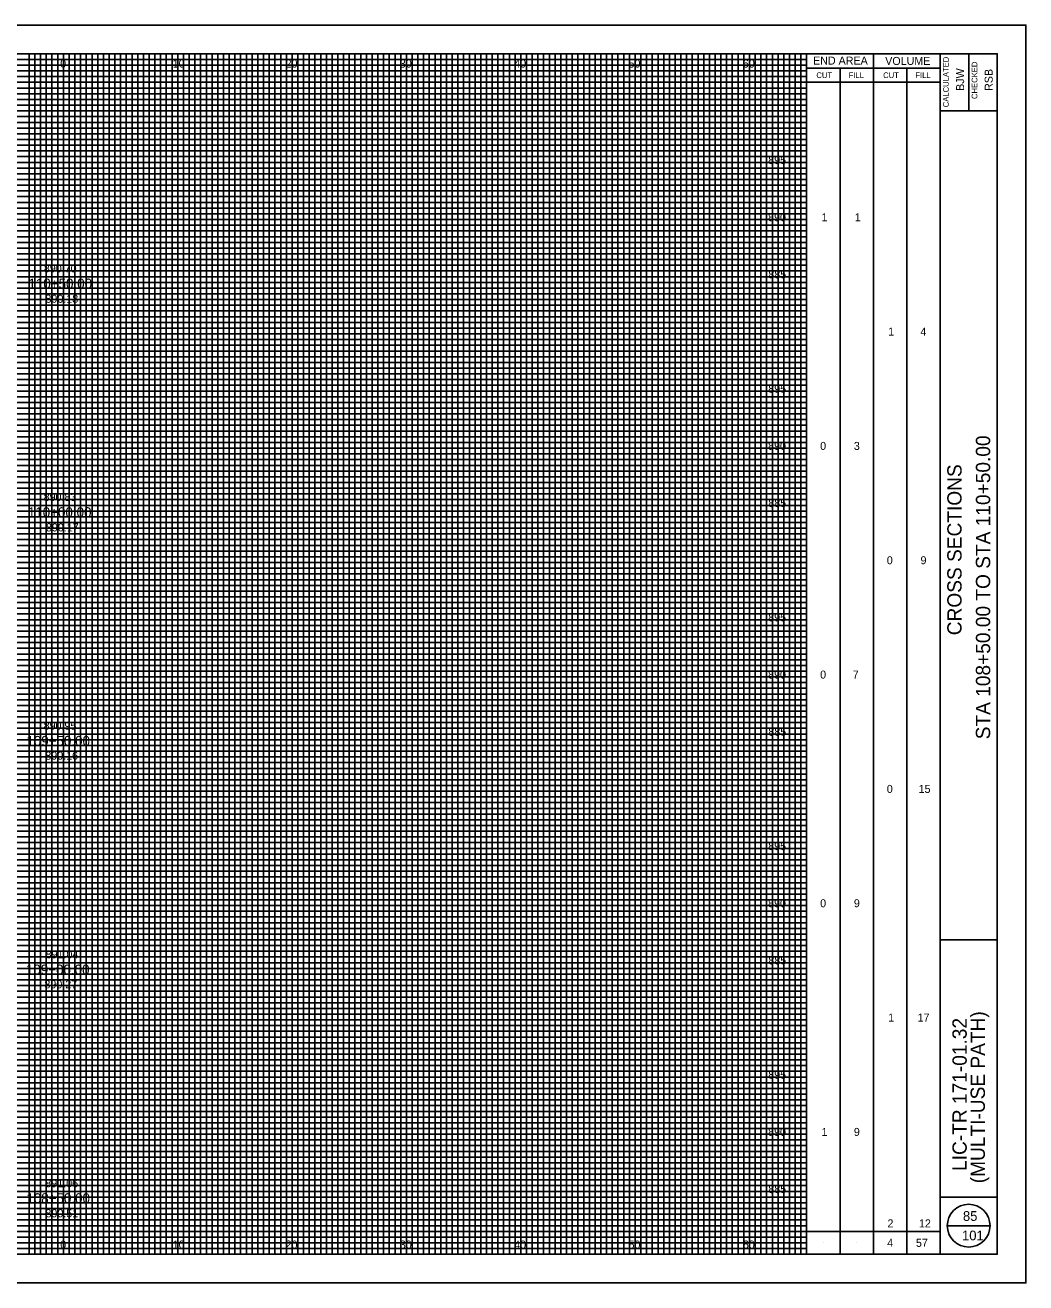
# Model space of a CAD drawing. Extents: x -10 to 160, y -2 to 3672.
# Drawn here: x 72.5 to 160, y 1837.5 to 1947.5 of the extents above; entities that cross this region are included whole.
import ezdxf

# ---------------------------------------------------------------- set-up
doc = ezdxf.new("R2010")
doc.units = 0
for name, color, linetype in [('SH_Border', 7, 'Continuous'), ('SH_Cut_Line', 7, 'Continuous'), ('SH_Data', 7, 'Continuous'), ('SH_Major_Grid_Line', 7, 'Continuous'), ('SH_Minor_Grid_Line', 7, 'Continuous'), ('SH_Text', 7, 'Continuous'), ('TX_P_10', 7, 'Continuous'), ('TX_X_10', 7, 'Continuous')]:
    doc.layers.add(name, color=color, linetype=linetype)

msp = doc.modelspace()

# ---------------------------------------------------------------- linework, layer by layer
at = {"layer": 'SH_Border'}
for p, q in [((152.5, 1840), (152.5, 1945)), ((155, 1945), (155, 1940)), ((152.5, 1940), (157.5, 1940)), ((152.5, 1867.5), (157.5, 1867.5)), ((152.5, 1845), (157.5, 1845))]:
    msp.add_line(p, q, dxfattribs=at)
msp.add_lwpolyline([(0, 1945), (157.5, 1945), (157.5, 1840), (0, 1840)], close=True, dxfattribs=at)
at = {"layer": 'SH_Cut_Line'}
msp.add_lwpolyline([(-10, 1837.5), (160, 1837.5), (160, 1947.5), (-10, 1947.5)], close=True, dxfattribs=at)
at = {"layer": 'SH_Data'}
for p, q in [((140.83, 1840), (140.83, 1945)), ((146.67, 1840), (146.67, 1945)), ((140.83, 1943.75), (152.5, 1943.75)), ((143.75, 1840), (143.75, 1943.75)), ((149.58, 1840), (149.58, 1943.75)), ((140.83, 1942.5), (152.5, 1942.5)), ((140.83, 1842), (152.5, 1842)), ((153.12, 1842.5), (156.88, 1842.5)), ((142.29, 1841), (142.29, 1841)), ((145.21, 1841), (145.21, 1841)), ((148.12, 1841), (148.12, 1841)), ((151.04, 1841), (151.04, 1841))]:
    msp.add_line(p, q, dxfattribs=at)
msp.add_circle((155, 1842.5), 1.87, dxfattribs=at)
at = {"layer": 'SH_Major_Grid_Line'}
for p, q in [((75.83, 1840), (75.83, 1945)), ((80.83, 1840), (80.83, 1945)), ((85.83, 1840), (85.83, 1945)), ((90.83, 1840), (90.83, 1945)), ((95.83, 1840), (95.83, 1945)), ((100.83, 1840), (100.83, 1945)), ((105.83, 1840), (105.83, 1945)), ((110.83, 1840), (110.83, 1945)), ((115.83, 1840), (115.83, 1945)), ((120.83, 1840), (120.83, 1945)), ((125.83, 1840), (125.83, 1945)), ((130.83, 1840), (130.83, 1945)), ((135.83, 1840), (135.83, 1945)), ((5.83, 1940), (140.83, 1940)), ((5.83, 1935), (140.83, 1935)), ((5.83, 1930), (140.83, 1930)), ((5.83, 1925), (140.83, 1925)), ((5.83, 1920), (140.83, 1920)), ((5.83, 1915), (140.83, 1915)), ((5.83, 1910), (140.83, 1910)), ((5.83, 1905), (140.83, 1905)), ((5.83, 1900), (140.83, 1900)), ((5.83, 1895), (140.83, 1895)), ((5.83, 1890), (140.83, 1890)), ((5.83, 1885), (140.83, 1885)), ((5.83, 1880), (140.83, 1880)), ((5.83, 1875), (140.83, 1875)), ((5.83, 1870), (140.83, 1870)), ((5.83, 1865), (140.83, 1865)), ((5.83, 1860), (140.83, 1860)), ((5.83, 1855), (140.83, 1855)), ((5.83, 1850), (140.83, 1850)), ((5.83, 1845), (140.83, 1845))]:
    msp.add_line(p, q, dxfattribs=at)
at = {"layer": 'SH_Minor_Grid_Line'}
for p, q in [((72.83, 1840), (72.83, 1945)), ((73.33, 1840), (73.33, 1945)), ((73.83, 1840), (73.83, 1945)), ((74.33, 1840), (74.33, 1945)), ((74.83, 1840), (74.83, 1945)), ((75.33, 1840), (75.33, 1945)), ((76.33, 1840), (76.33, 1945)), ((76.83, 1840), (76.83, 1945)), ((77.33, 1840), (77.33, 1945)), ((77.83, 1840), (77.83, 1945)), ((78.33, 1840), (78.33, 1945)), ((78.83, 1840), (78.83, 1945)), ((79.33, 1840), (79.33, 1945)), ((79.83, 1840), (79.83, 1945)), ((80.33, 1840), (80.33, 1945)), ((81.33, 1840), (81.33, 1945)), ((81.83, 1840), (81.83, 1945)), ((82.33, 1840), (82.33, 1945)), ((82.83, 1840), (82.83, 1945)), ((83.33, 1840), (83.33, 1945)), ((83.83, 1840), (83.83, 1945)), ((84.33, 1840), (84.33, 1945)), ((84.83, 1840), (84.83, 1945)), ((85.33, 1840), (85.33, 1945)), ((86.33, 1840), (86.33, 1945)), ((86.83, 1840), (86.83, 1945)), ((87.33, 1840), (87.33, 1945)), ((87.83, 1840), (87.83, 1945)), ((88.33, 1840), (88.33, 1945)), ((88.83, 1840), (88.83, 1945)), ((89.33, 1840), (89.33, 1945)), ((89.83, 1840), (89.83, 1945)), ((90.33, 1840), (90.33, 1945)), ((91.33, 1840), (91.33, 1945)), ((91.83, 1840), (91.83, 1945)), ((92.33, 1840), (92.33, 1945)), ((92.83, 1840), (92.83, 1945)), ((93.33, 1840), (93.33, 1945)), ((93.83, 1840), (93.83, 1945)), ((94.33, 1840), (94.33, 1945)), ((94.83, 1840), (94.83, 1945)), ((95.33, 1840), (95.33, 1945)), ((96.33, 1840), (96.33, 1945)), ((96.83, 1840), (96.83, 1945)), ((97.33, 1840), (97.33, 1945)), ((97.83, 1840), (97.83, 1945)), ((98.33, 1840), (98.33, 1945)), ((98.83, 1840), (98.83, 1945)), ((99.33, 1840), (99.33, 1945)), ((99.83, 1840), (99.83, 1945)), ((100.33, 1840), (100.33, 1945)), ((101.33, 1840), (101.33, 1945)), ((101.83, 1840), (101.83, 1945)), ((102.33, 1840), (102.33, 1945)), ((102.83, 1840), (102.83, 1945)), ((103.33, 1840), (103.33, 1945)), ((103.83, 1840), (103.83, 1945)), ((104.33, 1840), (104.33, 1945)), ((104.83, 1840), (104.83, 1945)), ((105.33, 1840), (105.33, 1945)), ((106.33, 1840), (106.33, 1945)), ((106.83, 1840), (106.83, 1945)), ((107.33, 1840), (107.33, 1945)), ((107.83, 1840), (107.83, 1945)), ((108.33, 1840), (108.33, 1945)), ((108.83, 1840), (108.83, 1945)), ((109.33, 1840), (109.33, 1945)), ((109.83, 1840), (109.83, 1945)), ((110.33, 1840), (110.33, 1945)), ((111.33, 1840), (111.33, 1945)), ((111.83, 1840), (111.83, 1945)), ((112.33, 1840), (112.33, 1945)), ((112.83, 1840), (112.83, 1945)), ((113.33, 1840), (113.33, 1945)), ((113.83, 1840), (113.83, 1945)), ((114.33, 1840), (114.33, 1945)), ((114.83, 1840), (114.83, 1945)), ((115.33, 1840), (115.33, 1945)), ((116.33, 1840), (116.33, 1945)), ((116.83, 1840), (116.83, 1945)), ((117.33, 1840), (117.33, 1945)), ((117.83, 1840), (117.83, 1945)), ((118.33, 1840), (118.33, 1945)), ((118.83, 1840), (118.83, 1945)), ((119.33, 1840), (119.33, 1945)), ((119.83, 1840), (119.83, 1945)), ((120.33, 1840), (120.33, 1945)), ((121.33, 1840), (121.33, 1945)), ((121.83, 1840), (121.83, 1945)), ((122.33, 1840), (122.33, 1945)), ((122.83, 1840), (122.83, 1945)), ((123.33, 1840), (123.33, 1945)), ((123.83, 1840), (123.83, 1945)), ((124.33, 1840), (124.33, 1945)), ((124.83, 1840), (124.83, 1945)), ((125.33, 1840), (125.33, 1945)), ((126.33, 1840), (126.33, 1945)), ((126.83, 1840), (126.83, 1945)), ((127.33, 1840), (127.33, 1945)), ((127.83, 1840), (127.83, 1945)), ((128.33, 1840), (128.33, 1945)), ((128.83, 1840), (128.83, 1945)), ((129.33, 1840), (129.33, 1945)), ((129.83, 1840), (129.83, 1945)), ((130.33, 1840), (130.33, 1945)), ((131.33, 1840), (131.33, 1945)), ((131.83, 1840), (131.83, 1945)), ((132.33, 1840), (132.33, 1945)), ((132.83, 1840), (132.83, 1945)), ((133.33, 1840), (133.33, 1945)), ((133.83, 1840), (133.83, 1945)), ((134.33, 1840), (134.33, 1945)), ((134.83, 1840), (134.83, 1945)), ((135.33, 1840), (135.33, 1945)), ((136.33, 1840), (136.33, 1945)), ((136.83, 1840), (136.83, 1945)), ((137.33, 1840), (137.33, 1945)), ((137.83, 1840), (137.83, 1945)), ((138.33, 1840), (138.33, 1945)), ((138.83, 1840), (138.83, 1945)), ((139.33, 1840), (139.33, 1945)), ((139.83, 1840), (139.83, 1945)), ((140.33, 1840), (140.33, 1945)), ((5.83, 1944.5), (140.83, 1944.5)), ((5.83, 1944), (140.83, 1944)), ((5.83, 1943.5), (140.83, 1943.5)), ((5.83, 1943), (140.83, 1943)), ((5.83, 1942.5), (140.83, 1942.5)), ((5.83, 1942), (140.83, 1942)), ((5.83, 1941.5), (140.83, 1941.5)), ((5.83, 1941), (140.83, 1941)), ((5.83, 1940.5), (140.83, 1940.5)), ((5.83, 1939.5), (140.83, 1939.5)), ((5.83, 1939), (140.83, 1939)), ((5.83, 1938.5), (140.83, 1938.5)), ((5.83, 1938), (140.83, 1938)), ((5.83, 1937.5), (140.83, 1937.5)), ((5.83, 1937), (140.83, 1937)), ((5.83, 1936.5), (140.83, 1936.5)), ((5.83, 1936), (140.83, 1936)), ((5.83, 1935.5), (140.83, 1935.5)), ((5.83, 1934.5), (140.83, 1934.5)), ((5.83, 1934), (140.83, 1934)), ((5.83, 1933.5), (140.83, 1933.5)), ((5.83, 1933), (140.83, 1933)), ((5.83, 1932.5), (140.83, 1932.5)), ((5.83, 1932), (140.83, 1932)), ((5.83, 1931.5), (140.83, 1931.5)), ((5.83, 1931), (140.83, 1931)), ((5.83, 1930.5), (140.83, 1930.5)), ((5.83, 1929.5), (140.83, 1929.5)), ((5.83, 1929), (140.83, 1929)), ((5.83, 1928.5), (140.83, 1928.5)), ((5.83, 1928), (140.83, 1928)), ((5.83, 1927.5), (140.83, 1927.5)), ((5.83, 1927), (140.83, 1927)), ((5.83, 1926.5), (140.83, 1926.5)), ((5.83, 1926), (140.83, 1926)), ((5.83, 1925.5), (140.83, 1925.5)), ((5.83, 1924.5), (140.83, 1924.5)), ((5.83, 1924), (140.83, 1924)), ((5.83, 1923.5), (140.83, 1923.5)), ((5.83, 1923), (140.83, 1923)), ((5.83, 1922.5), (140.83, 1922.5)), ((5.83, 1922), (140.83, 1922)), ((5.83, 1921.5), (140.83, 1921.5)), ((5.83, 1921), (140.83, 1921)), ((5.83, 1920.5), (140.83, 1920.5)), ((5.83, 1919.5), (140.83, 1919.5)), ((5.83, 1919), (140.83, 1919)), ((5.83, 1918.5), (140.83, 1918.5)), ((5.83, 1918), (140.83, 1918)), ((5.83, 1917.5), (140.83, 1917.5)), ((5.83, 1917), (140.83, 1917)), ((5.83, 1916.5), (140.83, 1916.5)), ((5.83, 1916), (140.83, 1916)), ((5.83, 1915.5), (140.83, 1915.5)), ((5.83, 1914.5), (140.83, 1914.5)), ((5.83, 1914), (140.83, 1914)), ((5.83, 1913.5), (140.83, 1913.5)), ((5.83, 1913), (140.83, 1913)), ((5.83, 1912.5), (140.83, 1912.5)), ((5.83, 1912), (140.83, 1912)), ((5.83, 1911.5), (140.83, 1911.5)), ((5.83, 1911), (140.83, 1911)), ((5.83, 1910.5), (140.83, 1910.5)), ((5.83, 1909.5), (140.83, 1909.5)), ((5.83, 1909), (140.83, 1909)), ((5.83, 1908.5), (140.83, 1908.5)), ((5.83, 1908), (140.83, 1908)), ((5.83, 1907.5), (140.83, 1907.5)), ((5.83, 1907), (140.83, 1907)), ((5.83, 1906.5), (140.83, 1906.5)), ((5.83, 1906), (140.83, 1906)), ((5.83, 1905.5), (140.83, 1905.5)), ((5.83, 1904.5), (140.83, 1904.5)), ((5.83, 1904), (140.83, 1904)), ((5.83, 1903.5), (140.83, 1903.5)), ((5.83, 1903), (140.83, 1903)), ((5.83, 1902.5), (140.83, 1902.5)), ((5.83, 1902), (140.83, 1902)), ((5.83, 1901.5), (140.83, 1901.5)), ((5.83, 1901), (140.83, 1901)), ((5.83, 1900.5), (140.83, 1900.5)), ((5.83, 1899.5), (140.83, 1899.5)), ((5.83, 1899), (140.83, 1899)), ((5.83, 1898.5), (140.83, 1898.5)), ((5.83, 1898), (140.83, 1898)), ((5.83, 1897.5), (140.83, 1897.5)), ((5.83, 1897), (140.83, 1897)), ((5.83, 1896.5), (140.83, 1896.5)), ((5.83, 1896), (140.83, 1896)), ((5.83, 1895.5), (140.83, 1895.5)), ((5.83, 1894.5), (140.83, 1894.5)), ((5.83, 1894), (140.83, 1894)), ((5.83, 1893.5), (140.83, 1893.5)), ((5.83, 1893), (140.83, 1893)), ((5.83, 1892.5), (140.83, 1892.5)), ((5.83, 1892), (140.83, 1892)), ((5.83, 1891.5), (140.83, 1891.5)), ((5.83, 1891), (140.83, 1891)), ((5.83, 1890.5), (140.83, 1890.5)), ((5.83, 1889.5), (140.83, 1889.5)), ((5.83, 1889), (140.83, 1889)), ((5.83, 1888.5), (140.83, 1888.5)), ((5.83, 1888), (140.83, 1888)), ((5.83, 1887.5), (140.83, 1887.5)), ((5.83, 1887), (140.83, 1887)), ((5.83, 1886.5), (140.83, 1886.5)), ((5.83, 1886), (140.83, 1886)), ((5.83, 1885.5), (140.83, 1885.5)), ((5.83, 1884.5), (140.83, 1884.5)), ((5.83, 1884), (140.83, 1884)), ((5.83, 1883.5), (140.83, 1883.5)), ((5.83, 1883), (140.83, 1883)), ((5.83, 1882.5), (140.83, 1882.5)), ((5.83, 1882), (140.83, 1882)), ((5.83, 1881.5), (140.83, 1881.5)), ((5.83, 1881), (140.83, 1881)), ((5.83, 1880.5), (140.83, 1880.5)), ((5.83, 1879.5), (140.83, 1879.5)), ((5.83, 1879), (140.83, 1879)), ((5.83, 1878.5), (140.83, 1878.5)), ((5.83, 1878), (140.83, 1878)), ((5.83, 1877.5), (140.83, 1877.5)), ((5.83, 1877), (140.83, 1877)), ((5.83, 1876.5), (140.83, 1876.5)), ((5.83, 1876), (140.83, 1876)), ((5.83, 1875.5), (140.83, 1875.5)), ((5.83, 1874.5), (140.83, 1874.5)), ((5.83, 1874), (140.83, 1874)), ((5.83, 1873.5), (140.83, 1873.5)), ((5.83, 1873), (140.83, 1873)), ((5.83, 1872.5), (140.83, 1872.5)), ((5.83, 1872), (140.83, 1872)), ((5.83, 1871.5), (140.83, 1871.5)), ((5.83, 1871), (140.83, 1871)), ((5.83, 1870.5), (140.83, 1870.5)), ((5.83, 1869.5), (140.83, 1869.5)), ((5.83, 1869), (140.83, 1869)), ((5.83, 1868.5), (140.83, 1868.5)), ((5.83, 1868), (140.83, 1868)), ((5.83, 1867.5), (140.83, 1867.5)), ((5.83, 1867), (140.83, 1867)), ((5.83, 1866.5), (140.83, 1866.5)), ((5.83, 1866), (140.83, 1866)), ((5.83, 1865.5), (140.83, 1865.5)), ((5.83, 1864.5), (140.83, 1864.5)), ((5.83, 1864), (140.83, 1864)), ((5.83, 1863.5), (140.83, 1863.5)), ((5.83, 1863), (140.83, 1863)), ((5.83, 1862.5), (140.83, 1862.5)), ((5.83, 1862), (140.83, 1862)), ((5.83, 1861.5), (140.83, 1861.5)), ((5.83, 1861), (140.83, 1861)), ((5.83, 1860.5), (140.83, 1860.5)), ((5.83, 1859.5), (140.83, 1859.5)), ((5.83, 1859), (140.83, 1859)), ((5.83, 1858.5), (140.83, 1858.5)), ((5.83, 1858), (140.83, 1858)), ((5.83, 1857.5), (140.83, 1857.5)), ((5.83, 1857), (140.83, 1857)), ((5.83, 1856.5), (140.83, 1856.5)), ((5.83, 1856), (140.83, 1856)), ((5.83, 1855.5), (140.83, 1855.5)), ((5.83, 1854.5), (140.83, 1854.5)), ((5.83, 1854), (140.83, 1854)), ((5.83, 1853.5), (140.83, 1853.5)), ((5.83, 1853), (140.83, 1853)), ((5.83, 1852.5), (140.83, 1852.5)), ((5.83, 1852), (140.83, 1852)), ((5.83, 1851.5), (140.83, 1851.5)), ((5.83, 1851), (140.83, 1851)), ((5.83, 1850.5), (140.83, 1850.5)), ((5.83, 1849.5), (140.83, 1849.5)), ((5.83, 1849), (140.83, 1849)), ((5.83, 1848.5), (140.83, 1848.5)), ((5.83, 1848), (140.83, 1848)), ((5.83, 1847.5), (140.83, 1847.5)), ((5.83, 1847), (140.83, 1847)), ((5.83, 1846.5), (140.83, 1846.5)), ((5.83, 1846), (140.83, 1846)), ((5.83, 1845.5), (140.83, 1845.5)), ((5.83, 1844.5), (140.83, 1844.5)), ((5.83, 1844), (140.83, 1844)), ((5.83, 1843.5), (140.83, 1843.5)), ((5.83, 1843), (140.83, 1843)), ((5.83, 1842.5), (140.83, 1842.5)), ((5.83, 1842), (140.83, 1842)), ((5.83, 1841.5), (140.83, 1841.5)), ((5.83, 1841), (140.83, 1841)), ((5.83, 1840.5), (140.83, 1840.5))]:
    msp.add_line(p, q, dxfattribs=at)

# ---------------------------------------------------------------- texts
at = {"layer": 'SH_Data'}
for s, height, p in [('END AREA', 0.7, (141.39, 1944.05)), ('VOLUME', 0.7, (147.7, 1944.02)), ('CUT', 0.5, (141.68, 1942.87)), ('FILL', 0.5, (144.5, 1942.87)), ('CUT', 0.5, (147.52, 1942.87)), ('FILL', 0.5, (150.34, 1942.87)), ('85', 0.85, (154.5, 1842.92)), ('101', 0.85, (154.42, 1841.22))]:
    msp.add_text(s, height=height, dxfattribs=at).set_placement(p)
for s, height, p in [('CALCULATED', 0.5, (153.26, 1940.32)), ('BJW', 0.7, (154.6, 1941.75)), ('CHECKED', 0.5, (155.76, 1941.04)), ('RSB', 0.7, (157.1, 1941.75)), ('STA 108+50.00 TO STA 110+50.00', 1.25, (156.88, 1885.04)), ('CROSS SECTIONS', 1.25, (154.38, 1894.14)), ('LIC-TR 171-01.32', 1.25, (154.83, 1847.29)), ('(MULTI-USE PATH)', 1.25, (156.42, 1846.21))]:
    msp.add_text(s, height=height, rotation=90, dxfattribs=at).set_placement(p)
at = {"layer": 'SH_Text'}
for s, height, p in [('0', 0.7, (75.55, 1943.79)), ('10', 0.7, (85.39, 1943.79)), ('20', 0.7, (95.26, 1943.79)), ('30', 0.7, (105.25, 1943.79)), ('40', 0.7, (115.25, 1943.79)), ('50', 0.7, (125.25, 1943.79)), ('60', 0.7, (135.25, 1943.79)), ('895', 0.7, (137.47, 1935.35)), ('890', 0.7, (137.46, 1930.35)), ('1', 0.7, (142.13, 1930.35)), ('1', 0.7, (145.04, 1930.35)), ('110+50.00', 0.875, (72.77, 1924.46)), ('885', 0.7, (137.48, 1925.35)), ('1', 0.7, (147.96, 1920.35)), ('4', 0.7, (150.78, 1920.35)), ('895', 0.7, (137.47, 1915.35)), ('890', 0.7, (137.46, 1910.35)), ('0', 0.7, (142.01, 1910.35)), ('3', 0.7, (144.96, 1910.35)), ('110+00.00', 0.875, (72.72, 1904.46)), ('885', 0.7, (137.48, 1905.35)), ('0', 0.7, (147.84, 1900.35)), ('9', 0.7, (150.79, 1900.35)), ('895', 0.7, (137.47, 1895.35)), ('890', 0.7, (137.46, 1890.35)), ('0', 0.7, (142.01, 1890.35)), ('7', 0.7, (144.86, 1890.35)), ('885', 0.7, (137.48, 1885.35)), ('109+50.00', 0.875, (72.59, 1884.46)), ('0', 0.7, (147.84, 1880.35)), ('15', 0.7, (150.62, 1880.35)), ('895', 0.7, (137.47, 1875.35)), ('890', 0.7, (137.46, 1870.35)), ('0', 0.7, (142.01, 1870.35)), ('9', 0.7, (144.96, 1870.35)), ('885', 0.7, (137.48, 1865.35)), ('109+00.00', 0.875, (72.55, 1864.46)), ('1', 0.7, (147.96, 1860.35)), ('17', 0.7, (150.53, 1860.35)), ('895', 0.7, (137.47, 1855.35)), ('890', 0.7, (137.46, 1850.35)), ('1', 0.7, (142.13, 1850.35)), ('9', 0.7, (144.96, 1850.35)), ('885', 0.7, (137.48, 1845.35)), ('108+50.00', 0.875, (72.59, 1844.46)), ('2', 0.7, (147.9, 1842.35)), ('12', 0.7, (150.65, 1842.35)), ('0', 0.7, (75.55, 1840.5)), ('10', 0.7, (85.39, 1840.5)), ('20', 0.7, (95.26, 1840.5)), ('30', 0.7, (105.25, 1840.5)), ('40', 0.7, (115.25, 1840.5)), ('50', 0.7, (125.25, 1840.5)), ('60', 0.7, (135.25, 1840.5)), ('4', 0.7, (147.87, 1840.65)), ('57', 0.7, (150.39, 1840.65))]:
    msp.add_text(s, height=height, dxfattribs=at).set_placement(p)
at = {"layer": 'TX_P_10'}
for s, p in [('890.70', (74.12, 1925.88)), ('890.83', (74.1, 1905.88)), ('890.95', (74.1, 1885.88)), ('891.04', (74.27, 1865.88)), ('891.06', (74.25, 1845.86))]:
    msp.add_text(s, height=0.7, dxfattribs=at).set_placement(p)
at = {"layer": 'TX_X_10'}
for s, p in [('890.18', (74.26, 1923.22)), ('890.17', (74.3, 1903.22)), ('890.16', (74.25, 1883.26)), ('890.27', (74.17, 1863.26)), ('890.51', (74.26, 1843.23))]:
    msp.add_text(s, height=0.7, dxfattribs=at).set_placement(p)

doc.saveas('drawing.dxf')
